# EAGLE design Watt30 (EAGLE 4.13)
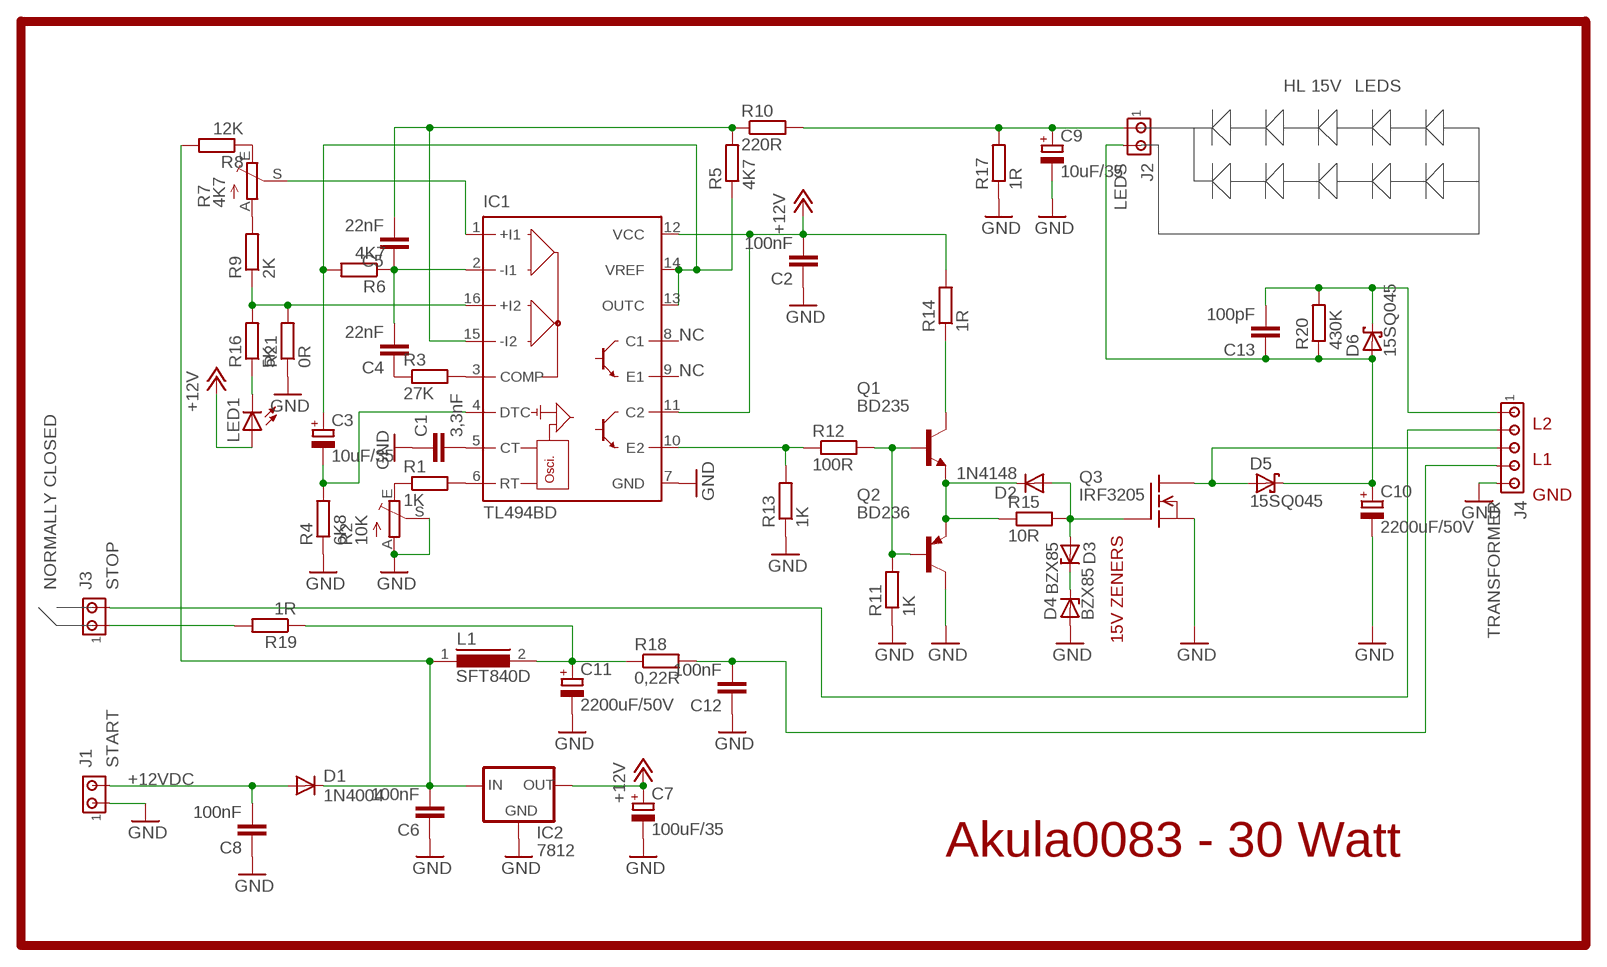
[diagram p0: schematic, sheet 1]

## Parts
C1  3,3nF  C-EU050-024X044  [C050-024X044]
C2  100nF  C-EU050-024X044  [C050-024X044]
C3  10uF/35  CPOL-EUE2-5  [E2-5]
C4  22nF  C-EU050-024X044  [C050-024X044]
C5  22nF  C-EU050-024X044  [C050-024X044]
C6  100nF  C-EU050-024X044  [C050-024X044]
C7  100uF/35  CPOL-EUE2.5-7  [E2,5-7]
C8  100nF  C-EU050-024X044  [C050-024X044]
C9  10uF/35  CPOL-EUE2-5  [E2-5]
C10  2200uF/50V  CPOL-EUE7.5-18  [E7,5-18]
C11  2200uF/50V  CPOL-EUE7.5-18  [E7,5-18]
C12  100nF  C-EU050-024X044  [C050-024X044]
C13  100pF  C-EU050-024X044  [C050-024X044]
D1  1N4004  [DO41-10]
D2  1N4148  [DO35-10]
D3  BZX85  [DO41Z10]
D4  BZX85  [DO41Z10]
D5  15SQ045  SCHOTTKY-DIODEP6T15  [P6T15]
D6  15SQ045  SCHOTTKY-DIODEP6T15  [P6T15]
IC1  TL494BD  [SO16]
IC2  7812  78XXL  [78XXL]
J1  START  MTA02-100  [10X02MTA]
J2  LEDS  MTA02-100  [10X02MTA]
J3  STOP  MTA02-100  [10X02MTA]
J4  TRANSFORMER  MTA05-156  [1X5MTA]
L1  SFT840D  [SFT840D]
LED1  LED5MM  [LED5MM]
Q1  BD235  [TO126]
Q2  BD236  [TO126]
Q3  IRF3205  IRF540  [TO220]
R1  1K  R-EU_R0805  [R0805]
R2  10K  TRIM_EU-B25U  [B25U]
R3  27K  R-EU_R0805  [R0805]
R4  6K8  R-EU_R0805  [R0805]
R5  4K7  R-EU_R0805  [R0805]
R6  4K7  R-EU_R0805  [R0805]
R7  4K7  TRIM_EU-B25U  [B25U]
R8  12K  R-EU_R0805  [R0805]
R9  2K  R-EU_R0805  [R0805]
R10  220R  R-EU_R0805  [R0805]
R11  1K  R-EU_R1210  [R1210]
R12  100R  R-EU_R1210  [R1210]
R13  1K  R-EU_R1210  [R1210]
R14  1R  R-EU_R1210  [R1210]
R15  10R  R-EU_R1210  [R1210]
R16  5K  R-EU_R0805  [R0805]
R17  1R  R-EU_R1210  [R1210]
R18  0,22R  R-EU_R1210  [R1210]
R19  1R  R-EU_R1210  [R1210]
R20  430K  R-EU_R1210  [R1210]
R21  0R  R-EU_R0805  [R0805]

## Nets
+12V: C2.2 C7.+ IC1.11(C2) IC1.12(VCC) IC2.OUT LED1.A R14.2
GND: C1.1 C2.1 C6.1 C7.- C8.1 C9.- C10.- C11.- C12.1 D4.A IC1.7(GND) IC2.GND J1.1 J4.5 Q2.2(C) Q3.3(S) R2.A R2.S R4.1 R11.1 R13.1 R17.1 R21.1
N$1: C1.2 IC1.5(CT)
N$2: IC1.6(RT) R1.2
N$3: Q1.2(C) R14.1
N$4: R1.1 R2.E
N$5: IC1.3(COMP) R3.2
N$6: C3.- IC1.4(DTC) R4.2
N$7: C3.+ IC1.13(OUTC) IC1.14(VREF) R5.1 R6.2
N$8: IC1.10(E2) R12.1 R13.2
N$9: C4.1 R3.1
N$10: C5.2 IC1.15(-I2) R5.2 R10.1
N$11: R7.E R8.1
N$12: R7.A R9.2
N$13: IC1.1(+I1) R7.S
N$14: D2.C Q1.1(E) Q2.1(E) R15.1
N$15: C9.+ J2.1 R10.2 R17.2
N$16: Q1.3(B) Q2.3(B) R11.2 R12.2
N$17: D3.C D4.C
N$18: C8.2 D1.A J1.2
N$19: D2.A D3.A Q3.1(G) R15.2
N$20: D5.A J4.3 Q3.2(D)
N$21: C6.2 D1.C IC2.IN L1.1 R8.2
N$22: C4.2 C5.1 IC1.2(-I1) R6.1
N$23: C10.+ C13.1 D5.C D6.A J2.2 R20.1
N$24: LED1.K(C) R16.1
N$25: C11.+ L1.2 R18.1 R19.1
N$26: C12.2 J4.4 R18.2
N$27: IC1.16(+I2) R9.1 R16.2 R21.2
N$29: C13.2 D6.C J4.1 R20.2
N$30: J3.1 R19.2
N$31: J3.2 J4.2
Unconnected: IC1.8(C1) IC1.9(E1)

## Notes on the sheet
- HL 15V | LEDS
- NC
- NC
- L2
- L1
- GND
- NORMALLY CLOSED
- 15V ZENERS
- +12VDC
- Akula0083 - 30 Watt

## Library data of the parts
C1 C2 C4-C6 C8 C12 C13 = rcl:C-EU: CAPACITOR, European symbol
C3 C7 C9-C11 = rcl:CPOL-EU: POLARIZED CAPACITOR, European symbol
D1 = diode:1N4004: DIODE
D2 = diode:1N4148: DIODE
D3 D4 = diode:BZX85: Z DIODE
D5 D6 = diode:SCHOTTKY-DIODE: Schottky Diode
IC1 = linear:TL494*: SWITCHMODE Pulse Width Modulation Control Circuit NCV494B http://onsemi.com tl494-d.pdf
IC2 = v-reg:78XXL: VOLTAGE REGULATOR
J1-J3 = con-amp:MTA02-100: AMP connector
J4 = con-amp:MTA05-156: AMP connector
L1 = inductors:SFT840D: INDUCTOR
LED1 = led:LED: LED
Q1 = transistor-npn:BD235*: NPN Transistor
Q2 = transistor-pnp:BD236: PNP Transistor
Q3 = transistor-fet:IRF540: N-Channel Enhancement MOSFET (HEXFET); 100V; 28A; 0,077Ohm
R1 R3-R6 R8-R21 = rcl:R-EU_: RESISTOR, European symbol
R2 R7 = pot:TRIM_EU-: POTENTIOMETER

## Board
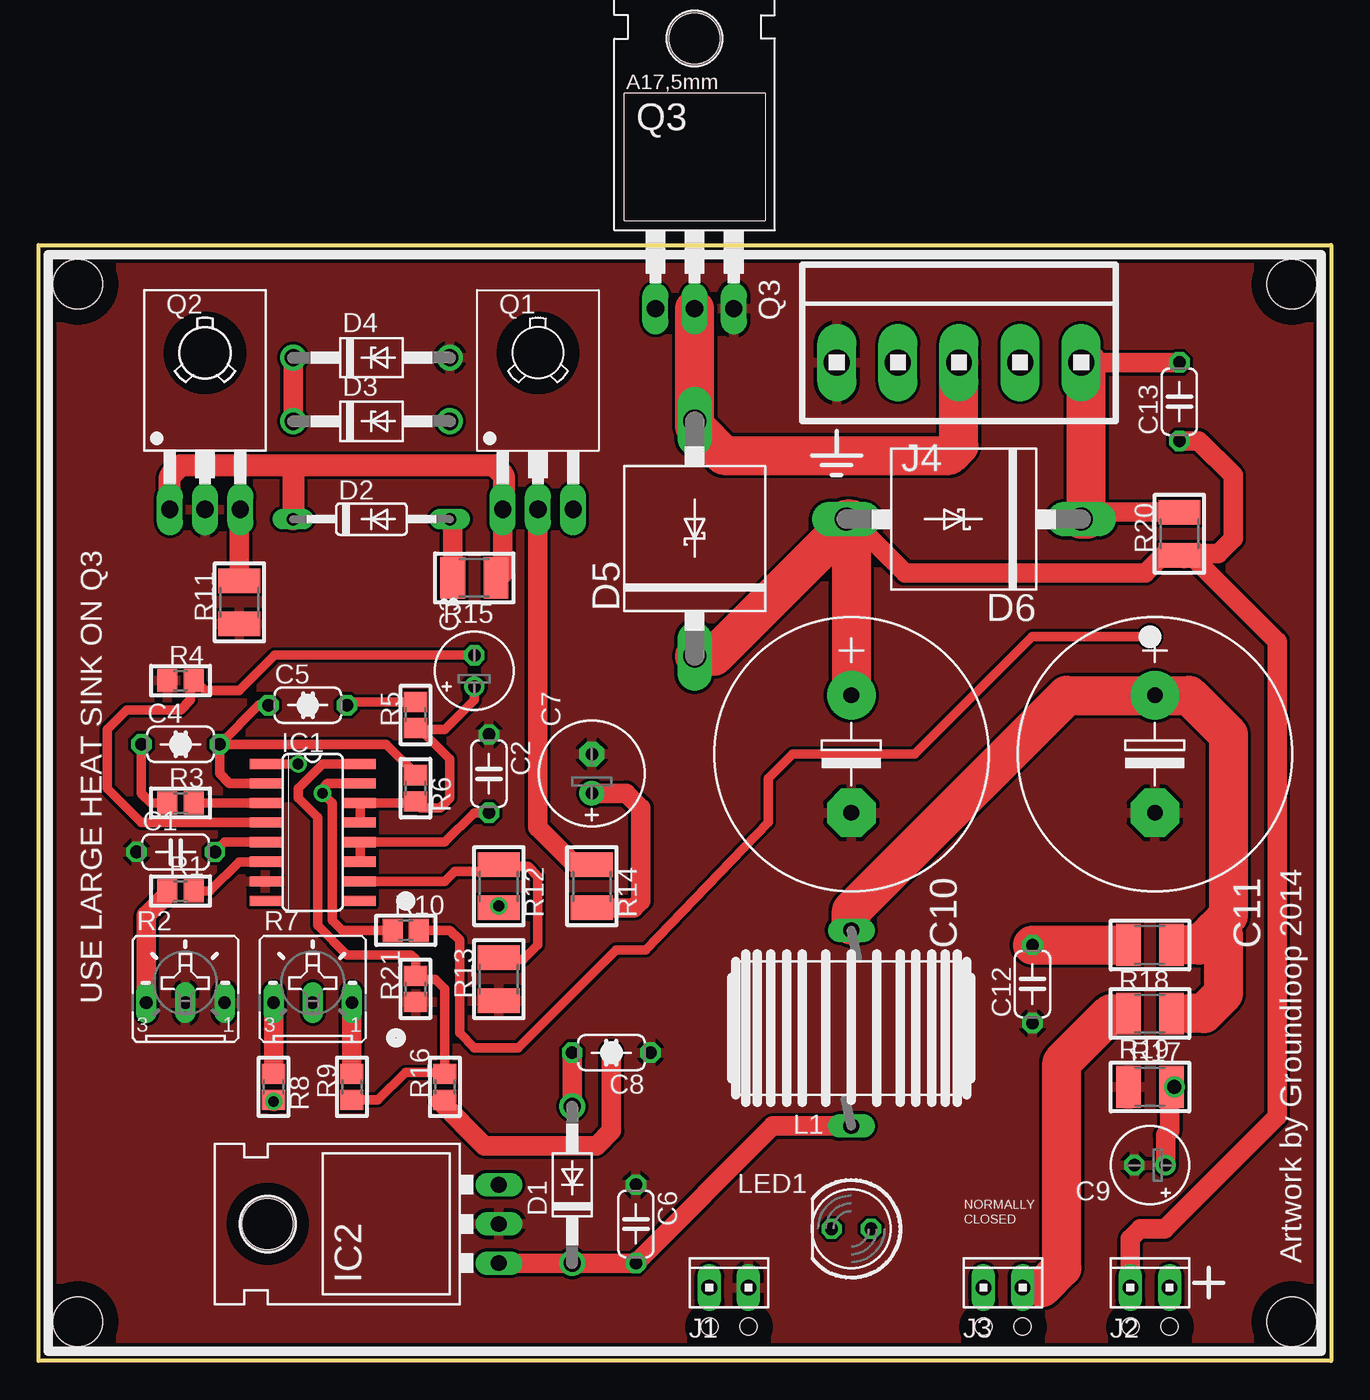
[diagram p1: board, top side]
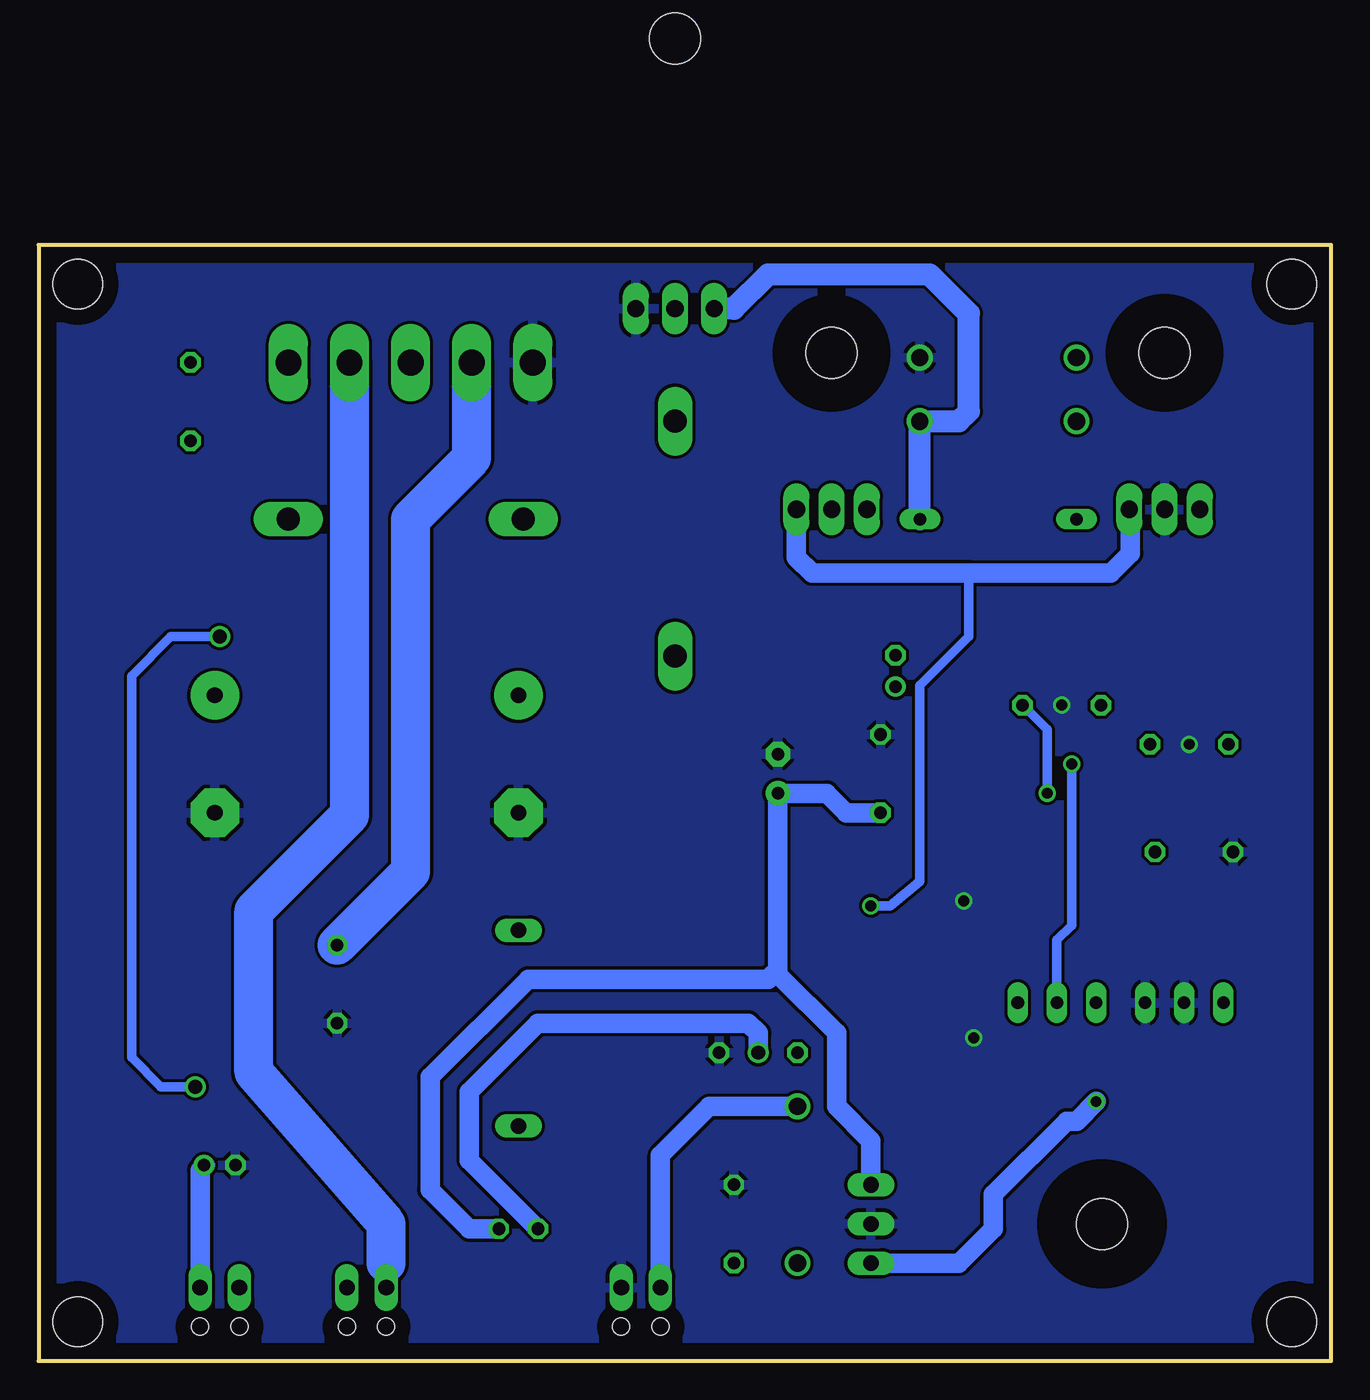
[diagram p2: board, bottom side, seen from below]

Size 83.82 x 72.39 mm. Coordinates in mm from the lower left corner, seen from the top.
Outline: 0,0 0,72.39 83.82,72.39 83.82,0 0,0
Copper layers (1*16): Top 0.035mm / dielectric 1.5mm / Bottom 0.035mm
Design rules "default": minimum track width 10mil, minimum drill 24mil, track to track 8mil, track to pad 8mil, pad to pad 8mil, via to via 8mil, smd to smd 8mil, copper to edge 40mil, drill to drill 8mil, minimum pad ring 10mil, minimum via ring 8mil, stop-mask expansion 4mil, vias tented up to drill 0mil, thermal gap 10mil
Holes 3.2 mm at 2.54,69.85 81.28,69.85 2.54,2.54 81.28,2.54
Holes 1.1 mm at 43.5,2.22 46.04,2.22 61.28,2.22 63.82,2.22 70.8,2.22 73.34,2.22
tKeepout: area 6.7,59.1 to 14.9,69.5; area 28.3,59.1 to 36.5,69.5; area 44.1,16.2 to 61.3,27

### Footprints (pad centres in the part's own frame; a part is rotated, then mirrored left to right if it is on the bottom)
C050-024X044 = drill 0.813 octagon: 1 -2.54,0; 2 2.54,0
E2-5 = drill 0.813 pad 1.27 round: + -1.016,0 | drill 0.813 pad 1.27 octagon: - 1.016,0
E2,5-7 = drill 0.813 pad 1.6 round: + -1.27,0 | drill 0.813 pad 1.6 octagon: - 1.27,0
E7,5-18 = drill 1.016 pad 3.15 round: + -3.81,0 | drill 1.016 pad 3.15 octagon: - 3.81,0
DO41-10 = drill 1.118 round: A 5.08,0; C -5.08,0
DO35-10 = drill 0.813 long: A 5.08,0; C -5.08,0
DO41Z10 = drill 1.118 round: A 5.08,0; C -5.08,0
P6T15 = drill 1.499 long: A 7.62,0; C -7.62,0
SO16 = smd 0.66 x 2.032: 1 -4.445,-3.073; 2 -3.175,-3.073; 3 -1.905,-3.073; 4 -0.635,-3.073; 5 0.635,-3.073; 6 1.905,-3.073; 7 3.175,-3.073; 8 4.445,-3.073; 9 4.445,3.073; 10 3.175,3.073; 11 1.905,3.073; 12 0.635,3.073; 13 -0.635,3.073; 14 -1.905,3.073; 15 -3.175,3.073; 16 -4.445,3.073
78XXL = drill 1.016 long: GND 0,-3.81; IN -2.54,-3.81; OUT 2.54,-3.81 | hole 3.302: 0,11.176
10X02MTA = drill 1.016 long: 1 1.27,0; 2 -1.27,0
1X5MTA = drill 1.676 long: 1 7.925,0; 2 3.962,0; 3 0,0; 4 -3.962,0; 5 -7.925,0
SFT840D = drill 1.016 long: 1 -6.35,0; 2 6.35,0
LED5MM = drill 0.813 octagon: A -1.27,0; K 1.27,0
TO126 = drill 1.118 long: 1 -2.286,-5.08; 2 0,-5.08; 3 2.286,-5.08 | hole 3.302: 0,5.08
TO220 = drill 1.118 long: 1 -2.54,-6.35; 2 0,-6.35; 3 2.54,-6.35 | hole 3.302: 0,11.176
R0805 = smd 1.3 x 1.5: 1 -0.85,0; 2 0.85,0
B25U = drill 0.813 long: A 2.54,-0.889; E -2.54,-0.889; S 0,-0.889
R1210 = smd 1.6 x 2.7: 1 -1.4,0; 2 1.4,0

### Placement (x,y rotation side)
C1  8.89,33.02 0 top
C2  29.21,38.1 270 top
C3  28.26,44.77 90 top
C4  9.21,40.01 0 top
C5  17.46,42.55 0 top
C6  38.73,8.89 270 top
C7  35.88,38.1 90 top
C8  37.15,20 180 top
C9  72.07,12.7 180 top
C10  52.7,39.37 270 top
C11  72.39,39.37 270 top
C12  64.45,24.45 90 top
C13  73.98,62.23 90 top
D1  34.61,11.43 90 top
D2  21.59,54.61 0 top
D3  21.59,60.96 0 top
D4  21.59,65.09 0 top
D5  42.55,53.34 90 top
D6  60.01,54.61 180 top
IC1  17.78,34.29 270 top
IC2  26.04,8.89 90 top
J1  44.77,4.76 0 top
J2  72.07,4.76 0 top
J3  62.55,4.76 0 top
J4  59.69,64.77 0 top
L1  52.7,21.59 90 top
LED1  52.7,8.57 180 top
Q1  32.38,60.33 0 top
Q2  10.79,60.33 0 top
Q3  42.55,74.61 0 top
R1  9.21,30.48 0 top
R2  9.53,24.13 0 top
R3  9.21,36.2 0 top
R4  9.21,44.13 0 top
R5  24.45,41.91 90 top
R6  24.45,37.15 270 top
R7  17.78,24.13 0 top
R8  15.24,17.78 270 top
R9  20.32,17.78 90 top
R10  23.81,27.94 0 top
R11  13.02,49.21 90 top
R12  29.84,30.8 270 top
R13  29.84,24.77 90 top
R14  35.88,30.8 270 top
R15  28.26,50.8 180 top
R16  26.35,17.78 90 top
R17  72.07,17.78 0 top
R18  72.07,26.99 180 top
R19  72.07,22.54 180 top
R20  73.98,53.66 90 top
R21  24.45,24.13 90 top

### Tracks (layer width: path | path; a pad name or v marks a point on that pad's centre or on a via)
+12V
  Top 0.61: IC1.11 20.95,32.38 20.85,32.49 IC1.12 26.35,33.66 28.26,35.56 C2.2
  Top 1.27: R14.2 38.6,29.4 39.05,29.84 39.05,35.88 38.1,36.83 C7.+
  Bottom 1.27: IC2.OUT 29.84,14.29 32.07,16.51 32.07,21.27 35.88,25.08 | 35.88,25.08 C7.+ 32.7,36.83 31.43,35.56 C2.2 | LED1.A 55.88,8.57 58.42,11.11 58.42,18.41 52.07,24.77 36.51,24.77 36.2,25.08 35.88,25.08
GND  (via drill 0.7)
  other vias: 23.18,20.95 17.46,42.55 9.21,40.01 23.81,29.84
  pour Top: 0.64,71.75 83.19,71.75 83.19,0.64 0.64,0.64
  pour Bottom: 0.64,71.75 83.19,71.75 83.19,0.64 0.64,0.64
N$1
  Top 0.61: IC1.5 12.06,33.66 C1.2
N$2
  Top 0.61: IC1.6 13.02,32.38 11.11,30.48 R1.2
N$3
  Top 1.27: Q1.2 32.38,34.61 34.61,32.38 35.56,32.38 35.75,32.2 R14.1
N$4
  Top 1.27: R1.1 8.36,30.27 6.99,28.89 R2.E
N$5
  Top 0.61: R3.2 IC1.3
N$6
  Top 0.61: IC1.4 6.67,34.92 4.45,37.15 4.45,40.96 5.71,42.23 9.21,42.23 9.84,42.86 9.84,43.81 10.16,44.13 | C3.- 15.3,45.78 13.02,43.5 10.79,43.5 10.16,44.13 | 10.16,44.13 R4.2
N$7
  Top 0.61: C3.+ 28.26,42.86 26.35,40.96 24.77,40.96 24.66,41.06 | 24.66,41.06 R5.1 | 24.66,41.06 26.67,39.05 26.67,36.51 26.04,35.88 24.77,35.88 24.45,36.2 | 24.45,36.2 R6.2 | 20.95,36.2 24.45,36.2 | 20.95,36.2 IC1.14 | IC1.13 20.85,36.09 20.95,36.2
N$8
  Top 0.61: 29.84,32.07 R12.1 | 29.84,32.07 31.75,32.07 32.38,31.43 32.38,26.99 31.43,26.04 29.84,26.04 R13.2 | IC1.10 26.35,31.11 26.99,31.75 29.84,31.75 29.84,32.07
N$9
  Top 0.61: C4.1 6.67,36.83 7.3,36.2 R3.1
N$10  (via drill 0.7)
  Top 0.61: C5.2 19.68,42.55 19.9,42.76 R5.2 | 20.95,37.47 IC1.15 18.73,37.47 18.41,37.15 v18.41,36.83 19.05,36.2 19.05,28.57 19.68,27.94 R10.1
  Bottom 0.61: C5.2 18.41,40.96 v18.41,36.83
N$11
  Top 1.27: R8.1 R7.E
N$12
  Top 1.27: R9.2 R7.A
N$13  (via drill 0.7)
  Top 0.61: v16.83,38.73 IC1.1
  Bottom 0.61: 17.78,23.18 R7.S 17.78,27.3 16.83,28.26 v16.83,38.73
N$14
  Top 1.27: R15.1 29.84,50.8 30.1,51.05 Q1.1
  Top 1.422: Q2.1 8.51,57.4 9.21,58.1 16.51,58.1 | 16.51,58.1 29.53,58.1 30.16,57.47 30.16,55.24 Q1.1 | 16.51,58.1 D2.C
N$15  (via drill 0.9)
  Top 0.61: v72.07,46.99 64.45,46.99 56.83,39.37 48.9,39.37 47.31,37.78 47.31,34.92 39.37,26.67 37.47,26.67 31.11,20.32 28.26,20.32 27.3,21.27 27.3,27.3 26.67,27.94 R10.2 | v73.66,17.78 R17.2
  Top 1.27: C9.+ 73.09,14.67 73.34,14.92 73.34,17.46 73.47,17.59 R17.2
  Bottom 0.61: v72.07,46.99 75.25,46.99 77.79,44.45 77.79,19.68 75.88,17.78 v73.66,17.78
  Bottom 1.27: C9.+ 73.03,12.7 73.34,12.38 J2.1
N$16  (via drill 0.7)
  Top 0.61: R12.2 29.34,29.4 v29.84,29.53
  Top 1.27: Q2.3 13.02,55.24 R11.2
  Bottom 0.61: v29.84,29.53 28.57,29.53 26.67,31.11 26.67,43.81 23.5,46.99 23.5,51.12
  Bottom 1.27: Q1.3 34.67,52.13 33.66,51.12 23.5,51.12 14.29,51.12 13.02,52.39 13.02,55.24 Q2.3
N$17
  Top 1.27: D3.C D4.C
N$18
  Top 1.27: D1.A C8.2
  Bottom 1.27: J1.2 43.5,13.34 40.32,16.51 D1.A
N$19
  Top 1.27: R15.2 26.86,54.42 D2.A
  Bottom 1.422: Q3.1 38.73,68.26 36.51,70.48 26.04,70.48 23.5,67.94 23.5,61.59 24.13,60.96 D3.A D2.A
N$20
  Top 2.54: J4.3 59.69,59.37 59.05,58.74 44.45,58.74 42.55,60.64 D5.A Q3.2
N$21  (via drill 0.7)
  Top 1.27: IC2.IN D1.C C6.2 47.62,15.24 L1.1 | v15.24,16.83 R8.2
  Bottom 1.27: IC2.IN 24.13,6.35 21.91,8.57 21.91,10.79 17.14,15.56 16.51,15.56 v15.24,16.83
N$22
  Top 0.61: IC1.2 12.38,37.47 11.75,38.1 C4.2 | R6.1 24.45,38.1 22.54,40.01 C4.2 | C5.1 14.29,42.55 C4.2
N$23
  Top 1.27: C13.1 75.25,59.69 77.47,57.47 77.47,53.34 76.52,52.39 74.61,52.39 | 74.61,52.39 74.3,52.07 74.11,52.26 R20.1 72.89,52.26 71.75,51.12 56.2,51.12 52.7,54.61 | J2.2 70.8,7.94 71.44,8.57 73.03,8.57 80.33,15.88 80.33,46.67 74.61,52.39
  Top 2.54: C10.+ 52.7,54.61 D6.A 52.39,54.29 43.81,45.72 D5.C
N$24  (via drill 0.9)
  Top 1.27: v37.15,20 37.15,14.92 36.2,13.97 28.89,13.97 26.04,16.83 26.14,16.93 R16.1
  Bottom 1.27: LED1.K 55.88,13.02 55.88,17.46 51.44,21.91 37.78,21.91 37.15,21.27 v37.15,20
N$25
  Top 1.27: 73.47,26.86 73.34,26.99 R18.1 73.98,26.99 | 74.61,22.54 R19.1 | L1.2 52.7,28.26
  Top 2.54: 73.98,26.99 75.25,26.99 76.2,27.94 | 76.2,27.94 77.15,28.89 77.15,40.64 74.61,43.18 C11.+ 66.67,43.18 52.7,29.21 52.7,28.26 | 74.61,22.54 75.56,22.54 76.83,23.81 76.83,27.62 76.52,27.62 76.2,27.94
N$26
  Top 1.27: 69.85,26.99 R18.2
  Top 2.54: C12.2 69.85,26.99
  Bottom 2.54: J4.4 55.73,58.57 59.69,54.61 59.69,31.75 C12.2
N$27
  Top 0.61: 24.45,25.08 24.77,24.77 25.72,24.77 26.35,24.13 26.35,18.73 | 20.95,38.73 IC1.16 18.41,38.73 16.83,37.15 16.83,36.51 18.1,35.24 18.1,28.26 20,26.35 24.13,26.35 24.45,26.04 24.45,25.08 | 24.45,25.08 R21.2 | R9.1 22.01,16.93 23.81,18.73 26.35,18.73 | 26.35,18.73 R16.2
N$29
  Top 1.27: 67.31,64.77 J4.1 C13.2 | R20.2 68.39,55.06 67.94,54.61
  Top 2.54: J4.1 67.94,64.77 67.94,54.61 D6.C
N$30
  Top 1.27: J3.1 65.09,4.76 | 70.8,22.54 R19.2 69.53,22.54
  Top 2.54: 65.09,4.76 66.36,6.03 66.36,19.37 69.53,22.54
N$31
  Bottom 1.27: J3.2 61.28,6.35
  Bottom 2.54: J4.2 63.65,35.41 69.85,29.21 69.85,18.73 61.28,8.89 61.28,6.35

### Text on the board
tPlace: Q3 | USE LARGE HEAT SINK ON Q3 | NORMALLY | CLOSED | Artwork by Groundloop 2014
